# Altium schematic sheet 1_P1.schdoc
size 429 x 307 mm; Symbol: Sheet-Symbol_A3; Device: Sheet-Symbol_A3; Company: 嘉立创EDA; Version: V1.0; Page Size: A3; @Project Name: CASA0021; @Page Count: 1; @Update Date: 2025-02-12; @Create Date: 2025-02-08; @Schematic Name: schematic diagram; @Page No: 1; @Page Name: P1; @Board Name: MCU_V0.2; @Create Time: 18:02:16; @Update Time: 12:16:57; Width: 1655; Height: 1170; Region Start: 1; X Region Count: 6; Y Region Count: 4; Blade Width: 10; Title Block Position: 3
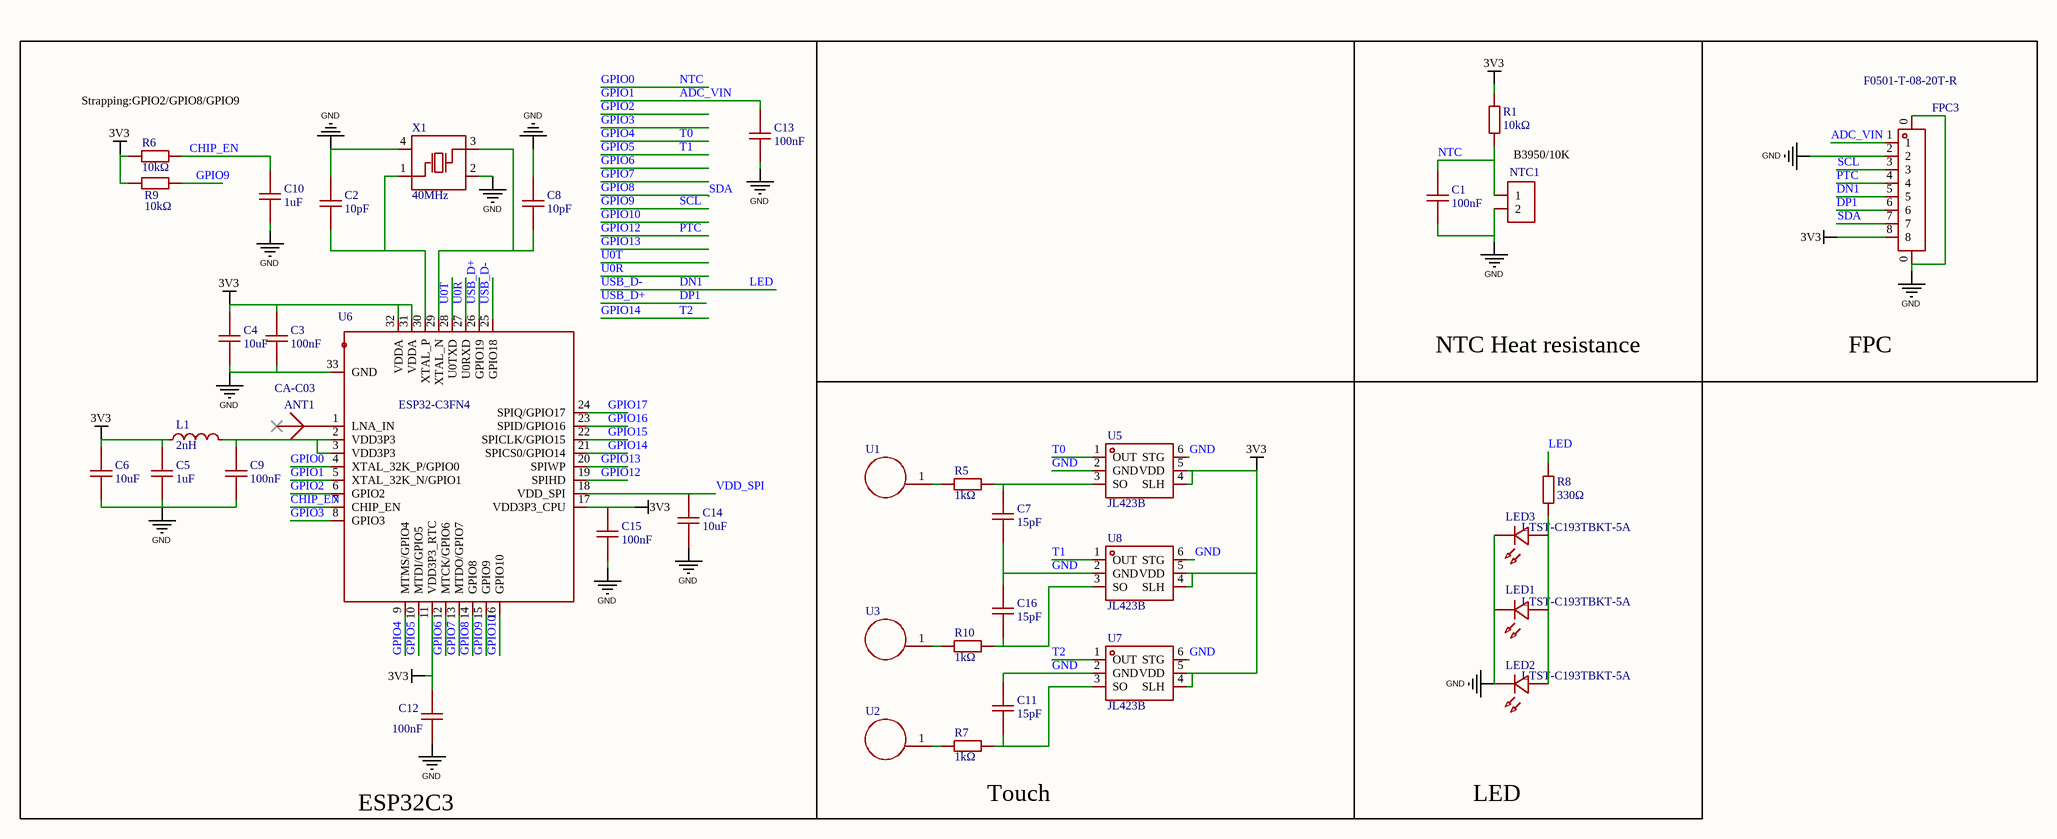
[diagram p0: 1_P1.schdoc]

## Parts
ANT1  CA-C03  [ANT-SMD_CA-C03]
C1  100nF  [C0603]
C2  10pF  [C0603]
C3  100nF  [C0603]
C4  10uF  [C0603]
C5  1uF  [C0603]
C6  10uF  [C0603]
C7  15pF  [C0603]
C8  10pF  [C0603]
C9  100nF  [C0603]
C10  1uF  [C0603]
C11  15pF  [C0603]
C12  100nF  [C0603]
C13  100nF  [C0603]
C14  10uF  [C0603]
C15  100nF  [C0603]
C16  15pF  [C0603]
FPC3  F0501-T-08-20T-R  [FPC-SMD_8P-P0.50_L4.4-W9.6]
L1  2nH  [L0603]
LED1  LTST-C193TBKT-5A  [LED0603-RD]
LED2  LTST-C193TBKT-5A  [LED0603-RD]
LED3  LTST-C193TBKT-5A  [LED0603-RD]
NTC1  (no value)  [HDR-TH_2P-P2.54-V-F]
R1  10kΩ  [R0603]
R5  1kΩ  [R0603]
R6  10kΩ  [R0603]
R7  1kΩ  [R0603]
R8  330Ω  [R0603]
R9  10kΩ  [R0603]
R10  1kΩ  [R0603]
U1  F10-10-6.5-0.4P  [TH_F10-10-6.5-0.4P]  (value not drawn)
U2  F10-10-6.5-0.4P  [TH_F10-10-6.5-0.4P]  (value not drawn)
U3  F10-10-6.5-0.4P  [TH_F10-10-6.5-0.4P]  (value not drawn)
U5  JL423B  [SOT-23-6_L2.9-W1.6-P0.95-LS2.8-BL-2]
U6  ESP32-C3FN4  [QFN-32_L5.0-W5.0-P0.50-BL-EP3.7]
U7  JL423B  [SOT-23-6_L2.9-W1.6-P0.95-LS2.8-BL-2]
U8  JL423B  [SOT-23-6_L2.9-W1.6-P0.95-LS2.8-BL-2]
X1  40MHz  [OSC-SMD_4P-L3.2-W2.5-BL_SIT8008BI]

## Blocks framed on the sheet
ESP32C3: ANT1 C2-C6 C8-C10 C12-C15 L1 R6 R9 U6 X1
NTC Heat resistance: C1 NTC1 R1
FPC: FPC3
Touch: C7 C11 C16 R5 R7 R10 U1-U3 U5 U7 U8
LED: LED1-LED3 R8

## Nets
3V3: C3.2 C4.2 C5.2 C6.2 C12.2 C15.2 FPC3.8 L1.1 R1.2 R6.1 R9.1 U5.4(SLH) U5.5(VDD) U6.11(VDD3P3_RTC) U6.17(VDD3P3_CPU) U6.31(VDDA) U6.32(VDDA) U7.4(SLH) U7.5(VDD) U8.4(SLH) U8.5(VDD)
GND: C1.1 C2.2 C3.1 C4.1 C5.1 C6.1 C7.1 C8.2 C9.1 C10.1 C11.2 C12.1 C13.2 C14.1 C15.1 C16.2 FPC3.0 FPC3.2 LED1.1(C) LED2.1(C) LED3.1(C) NTC1.2 U5.2(GND) U5.6(STG) U6.33(GND) U7.2(GND) U7.6(STG) U8.2(GND) U8.6(STG) X1.2(GND) X1.4(GND)
ADC_VIN: C13.1 FPC3.1 U6.5(XTAL_32K_N/GPIO1)  [also labelled GPIO1]
CHIP_EN: C10.2 R6.2 U6.7(CHIP_EN)
DN1: FPC3.5 R8.1 U6.25(GPIO18)  [also labelled LED, USB_D-]
DP1: FPC3.6 U6.26(GPIO19)  [also labelled USB_D+]
GPIO0: C1.2 NTC1.1 R1.1 U6.4(XTAL_32K_P/GPIO0)  [also labelled NTC]
GPIO2: U6.6(GPIO2)
GPIO3: U6.8(GPIO3)
GPIO4: U5.1(OUT) U6.9(MTMS/GPIO4)  [also labelled T0]
GPIO5: U6.10(MTDI/GPIO5) U8.1(OUT)  [also labelled T1]
GPIO6: U6.12(MTCK/GPIO6)
GPIO7: U6.13(MTDO/GPIO7)
GPIO8: FPC3.7 U6.14(GPIO8)  [also labelled SDA]
GPIO9: FPC3.3 R9.2 U6.15(GPIO9)  [also labelled SCL]
GPIO10: U6.16(GPIO10)
GPIO12: FPC3.4 U6.19(SPIHD)  [also labelled PTC]
GPIO13: U6.20(SPIWP)
GPIO14: U6.21(SPICS0/GPIO14) U7.1(OUT)  [also labelled T2]
GPIO15: U6.22(SPICLK/GPIO15)
GPIO16: U6.23(SPID/GPIO16)
GPIO17: U6.24(SPIQ/GPIO17)
U0R: U6.27(U0RXD)
U0T: U6.28(U0TXD)
VDD_SPI: C14.2 U6.18(VDD_SPI)
NetANT1_2: ANT1.2(ANT) U6.1(LNA_IN)
NetC2_1: C2.1 U6.30(XTAL_P) X1.1(OSC1)
NetC7_2: C7.2 R5.2 U5.3(SO)
NetC8_1: C8.1 U6.29(XTAL_N) X1.3(OSC2)
NetC9_2: C9.2 L1.2 U6.2(VDD3P3) U6.3(VDD3P3)
NetC11_1: C11.1 R7.2 U7.3(SO)
NetC16_1: C16.1 R10.2 U8.3(SO)
NetLED1_2: LED1.2(A) LED2.2(A) LED3.2(A) R8.2
NetR5_1: R5.1 U1.1
NetR7_1: R7.1 U2.1
NetR10_1: R10.1 U3.1

Not connected (* = marked no-connect by the designer): ANT1 1*

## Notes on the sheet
- Strapping:GPIO2/GPIO8/GPIO9
- B3950/10K

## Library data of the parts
ANT1 = CA-C03: Add into BOM: yes
C1 C13 = CGA0603X7R104K500JT: Manufacturer: HRE(芯声); Symbol: CapAcitance; Add into BOM: yes; Tolerance: ±10%; Voltage Rated: 50V; Temperature Coefficient: X7R
C2 = CC0603KRNPO9BN100: Manufacturer: YAGEO(国巨); Symbol: CapAcitance; Add into BOM: yes; Tolerance: ±10%; Voltage Rated: 50V; Temperature Coefficient: NP0
C3 C9 C12 C15 = CC0603KRX7R9BB104: Manufacturer: YAGEO(国巨); Symbol: CapAcitance; Add into BOM: yes; Tolerance: ±10%; Voltage Rated: 50V; Temperature Coefficient: X7R
C4 C6 C14 = CL10A106KP8NNNC: Manufacturer: SAMSUNG(三星); Symbol: CapAcitance; Add into BOM: yes; Tolerance: ±10%; Voltage Rated: 10V; Temperature Coefficient: X5R
C5 C10 = CL10A105KA8NNNC: Manufacturer: SAMSUNG(三星); Symbol: CapAcitance; Add into BOM: yes; Tolerance: ±10%; Voltage Rated: 25V; Temperature Coefficient: X5R
C7 C11 C16 = CC0603JRNPO9BN150: Manufacturer: YAGEO(国巨); Symbol: CapAcitance; Add into BOM: yes; Tolerance: ±5%; Voltage Rated: 50V; Temperature Coefficient: NP0
C8 = CC0603FRNPO9BN100: Manufacturer: YAGEO(国巨); Symbol: CapAcitance; Add into BOM: yes; Tolerance: ±1%; Voltage Rated: 50V; Temperature Coefficient: NP0
FPC3 = F0501-T-08-20T-R: Manufacturer: XFCN(兴飞); Add into BOM: yes; Locking Feature: 抽屉式; Number of Contacts: 8P; Pitch: 0.5mm
L1 = SDCL1608C2N0STDF: Manufacturer: Sunlord(顺络); Symbol: SDCL1005C10NJTDFM01; Add into BOM: yes
LED1-LED3 = LTST-C193TBKT-5A: Manufacturer: LITEON(光宝); Symbol: LED_B; Convert to PCB: yes; Emitted Color: 蓝色; Forward Voltage (VF): 2.8V; Power Dissipation: 76mW; Forward Current: 5mA; Dominant Wavelength: 465nm~475nm; Peak Wavelength: 468nm; Lens Color: 无色透明透镜; Luminous Intensity: 15mcd; Viewing Angle: 130°
NTC1 = HDR-F_2.54_1x2P: Manufacturer: BOOMELE(博穆精密); Manufacturer Part: 2.54-1*2P母; Symbol: Header-Female-2.54_1x2; Convert to PCB: yes
R1 R6 R9 = 0603WAF1002T5E: Manufacturer: UNI-ROYAL(厚声); Symbol: 电阻; Add into BOM: yes; Tolerance: ±1%; Power(Watts): 100mW; Overload Voltage (Max): 75V; Temperature Coefficient: ±100ppm/℃
R5 R7 R10 = 0603WAF1001T5E: Manufacturer: UNI-ROYAL(厚声); Symbol: 电阻; Add into BOM: yes; Tolerance: ±1%; Power(Watts): 100mW; Overload Voltage (Max): 75V; Temperature Coefficient: ±100ppm/℃
R8 = 0603WAF3300T5E: Manufacturer: UNI-ROYAL(厚声); Symbol: 电阻; Add into BOM: yes; Tolerance: ±1%; Power(Watts): 100mW; Overload Voltage (Max): 75V; Temperature Coefficient: ±100ppm/℃
U1-U3 = F10-10-6.5-0.4P: Manufacturer: Sam&wing(芯网); Symbol: 触摸弹簧 H10.0MM; Add into BOM: yes
U5 U7 U8 = JL423B: Add into BOM: yes
U6 = ESP32-C3FN4: Manufacturer: ESPRESSIF(乐鑫); Add into BOM: yes
X1 = X322540MPB4SI: Manufacturer: YXC(扬兴晶振); Add into BOM: yes; Crystal Type: 贴片无源晶振; Frequency Tolerance: ±10ppm; Frequency Stability: ±30ppm; Load Capacitance: 15pF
